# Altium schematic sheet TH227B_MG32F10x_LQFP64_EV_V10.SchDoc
size 309 x 233 mm
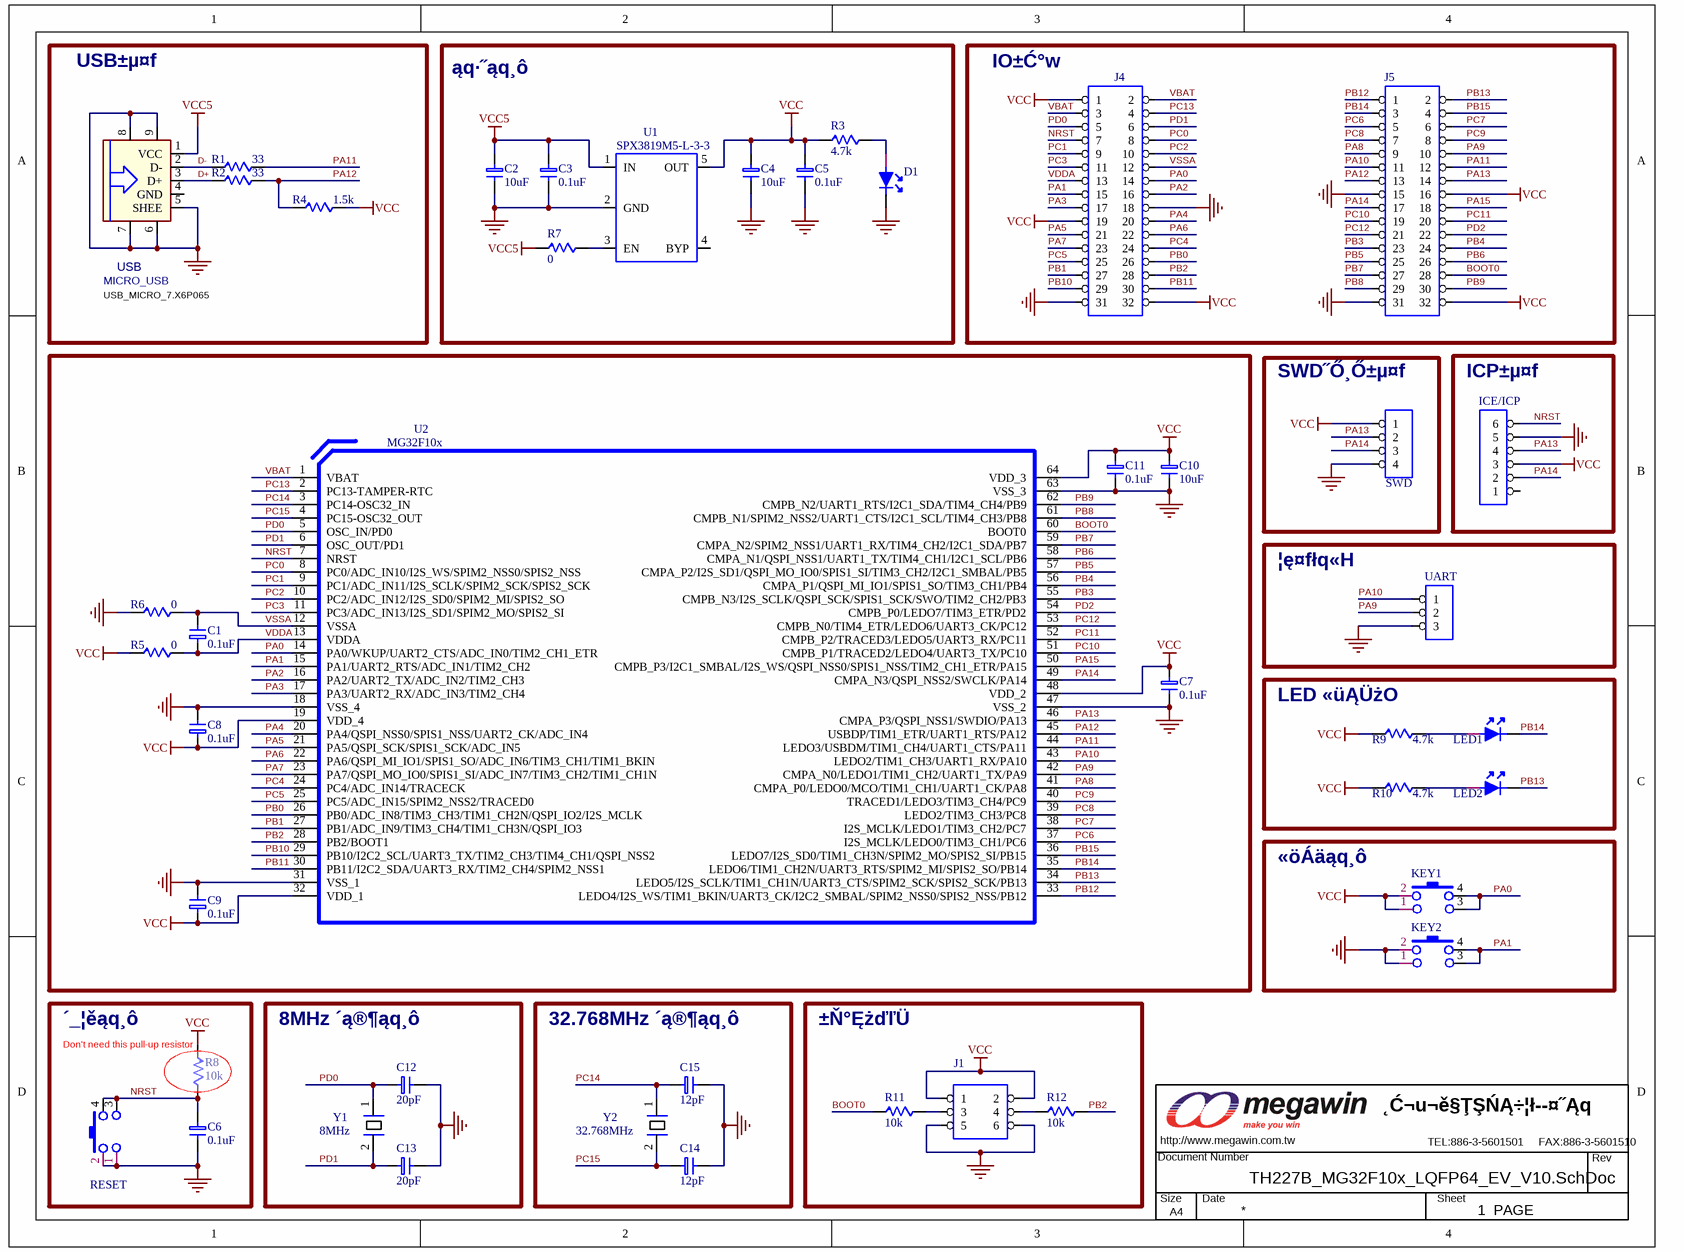
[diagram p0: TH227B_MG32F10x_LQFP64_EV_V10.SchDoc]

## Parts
C1  0.1uF  [0603_C]
C2  10uF  [0805_C]
C3  0.1uF  [0603_C]
C4  10uF  [0805_C]
C5  0.1uF  [0603_C]
C6  0.1uF  [0603_C]
C7  0.1uF  [0603_C]
C8  0.1uF  [0603_C]
C9  0.1uF  [0603_C]
C10  10uF  [0805_C]
C11  0.1uF  [0603_C]
C12  20pF  [0603_C]
C13  20pF  [0603_C]
C14  12pF  [0603_C]
C15  12pF  [0603_C]
D1  (no value)  [0805_LED_S1]
ICE/ICP  (no value)  [PS6P254F_90]
J1  CON3X2  [HDR-3X2]  (value not drawn)
J4  CON16X2  [HDR2X16_MR]  (value not drawn)
J5  CON16X2  [HDR2X16_MR]  (value not drawn)
KEY1  SW-PB4  [TSW DIP-6*6*6]  (value not drawn)
KEY2  SW-PB4  [TSW DIP-6*6*6]  (value not drawn)
LED1  (no value)  [0805_LED_S1]
LED2  (no value)  [0805_LED_S1]
MW1  MW-A4  [MEGAWIN_3.4]  (value not drawn)  (no BOM)
R1  33  [0603_R]
R2  33  [0603_R]
R3  4.7k  [0603_R]
R4  1.5k  [0603_R]
R5  0  [0603_R]
R6  0  [0603_R]
R7  0  [0603_R]
R8  10k  [0603_R]
R9  4.7k  [0603_R]
R10  4.7k  [0603_R]
R11  10k  [0603_R]
R12  10k  [0603_R]
RESET  SW-PB4  [TSW DIP-6*6*6]  (value not drawn)
SWD  CON4  [HDR-1X4]  (value not drawn)
U1  SPX3819M5-L-3-3  [SOT-23-5]
U2  MG32F10x  [LQFP64]
UART  CON3  [HDR-1X3]  (value not drawn)
USB  MICRO_USB  [USB5-micro_B-«Ř­ĘMRUSB-5B-D17xx-]
Y1  8MHz  [LC-HC-49S]
Y2  32.768MHz  [XTAL-3X8H]

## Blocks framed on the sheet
USB±µ¤f: R1 R2 R4 USB
ąq·˝ąq¸ô: C2-C5 D1 R3 R7 U1
IO±Ć°w: J4 J5
SWD˝Ő¸Ő±µ¤f: SWD
ICP±µ¤f: ICE/ICP
¦ę¤fłq«H: UART
LED «üĄÜżO: LED1 LED2 R9 R10
«öÁäąq¸ô: KEY1 KEY2
´_¦ěąq¸ô: C6 R8 RESET
8MHz ´ą®¶ąq¸ô: C12 C13 Y1
32.768MHz ´ą®¶ąq¸ô: C14 C15 Y2
±Ň°ĘżďľÜ: J1 R11 R12

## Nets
GND_POWER: C2.2 C3.2 C4.2 C5.2 C6.2 C7.2 C8.2 C9.2 C10.2 C11.2 C12.2 C13.2 C14.2 C15.2 D1.2 ICE/ICP.5 J1.5 J1.6 J4.18 J4.31 J5.15 J5.31 KEY2.1 KEY2.2 R6.1 RESET.1 RESET.2 SWD.4 U1.2(GND) U2.18(VSS_4) U2.31(VSS_1) U2.47(VSS_2) U2.63(VSS_3) UART.3 USB.5(SHEE) USB.6 USB.7 USB.8 USB.9
VCC: C4.1 C5.1 C7.1 C8.1 C9.1 C10.1 C11.1 ICE/ICP.3 J1.1 J1.2 J4.1 J4.19 J4.32 J5.16 J5.32 KEY1.1 KEY1.2 R3.1 R4.2 R5.1 R8.1 R9.1 R10.1 SWD.1 U1.5(OUT) U2.19(VDD_4) U2.32(VDD_1) U2.48(VDD_2) U2.64(VDD_3)
VCC5: C2.1 C3.1 R7.1 U1.1(IN) USB.1(VCC)
BOOT0: J5.28 R11.1 U2.60(BOOT0)
D+: R2.1 USB.3(D+)
D-: R1.1 USB.2(D-)
NRST: C6.1 ICE/ICP.6 J4.7 R8.2 RESET.3 RESET.4 U2.7(NRST)
PA0: J4.14 KEY1.3 KEY1.4 U2.14(PA0/WKUP/UART2_CTS/ADC_IN0/TIM2_CH1_ETR)
PA1: J4.15 KEY2.3 KEY2.4 U2.15(PA1/UART2_RTS/ADC_IN1/TIM2_CH2)
PA2: J4.16 U2.16(PA2/UART2_TX/ADC_IN2/TIM2_CH3)
PA3: J4.17 U2.17(PA3/UART2_RX/ADC_IN3/TIM2_CH4)
PA4: J4.20 U2.20(PA4/QSPI_NSS0/SPIS1_NSS/UART2_CK/ADC_IN4)
PA5: J4.21 U2.21(PA5/QSPI_SCK/SPIS1_SCK/ADC_IN5)
PA6: J4.22 U2.22(PA6/QSPI_MI_IO1/SPIS1_SO/ADC_IN6/TIM3_CH1/TIM1_BKIN)
PA7: J4.23 U2.23(PA7/QSPI_MO_IO0/SPIS1_SI/ADC_IN7/TIM3_CH2/TIM1_CH1N)
PA8: J5.9 U2.41(CMPA_P0/LEDO0/MCO/TIM1_CH1/UART1_CK/PA8)
PA9: J5.10 U2.42(CMPA_N0/LEDO1/TIM1_CH2/UART1_TX/PA9) UART.2
PA10: J5.11 U2.43(LEDO2/TIM1_CH3/UART1_RX/PA10) UART.1
PA11: J5.12 R1.2 U2.44(LEDO3/USBDM/TIM1_CH4/UART1_CTS/PA11)
PA12: J5.13 R2.2 R4.1 U2.45(USBDP/TIM1_ETR/UART1_RTS/PA12)
PA13: ICE/ICP.4 J5.14 SWD.2 U2.46(CMPA_P3/QSPI_NSS1/SWDIO/PA13)
PA14: ICE/ICP.2 J5.17 SWD.3 U2.49(CMPA_N3/QSPI_NSS2/SWCLK/PA14)
PA15: J5.18 U2.50(CMPB_P3/I2C1_SMBAL/I2S_WS/QSPI_NSS0/SPIS1_NSS/TIM2_CH1_ETR/PA15)
PB0: J4.26 U2.26(PB0/ADC_IN8/TIM3_CH3/TIM1_CH2N/QSPI_IO2/I2S_MCLK)
PB1: J4.27 U2.27(PB1/ADC_IN9/TIM3_CH4/TIM1_CH3N/QSPI_IO3)
PB2: J4.28 R12.2 U2.28(PB2/BOOT1)
PB3: J5.23 U2.55(CMPB_N3/I2S_SCLK/QSPI_SCK/SPIS1_SCK/SWO/TIM2_CH2/PB3)
PB4: J5.24 U2.56(CMPA_P1/QSPI_MI_IO1/SPIS1_SO/TIM3_CH1/PB4)
PB5: J5.25 U2.57(CMPA_P2/I2S_SD1/QSPI_MO_IO0/SPIS1_SI/TIM3_CH2/I2C1_SMBAL/PB5)
PB6: J5.26 U2.58(CMPA_N1/QSPI_NSS1/UART1_TX/TIM4_CH1/I2C1_SCL/PB6)
PB7: J5.27 U2.59(CMPA_N2/SPIM2_NSS1/UART1_RX/TIM4_CH2/I2C1_SDA/PB7)
PB8: J5.29 U2.61(CMPB_N1/SPIM2_NSS2/UART1_CTS/I2C1_SCL/TIM4_CH3/PB8)
PB9: J5.30 U2.62(CMPB_N2/UART1_RTS/I2C1_SDA/TIM4_CH4/PB9)
PB10: J4.29 U2.29(PB10/I2C2_SCL/UART3_TX/TIM2_CH3/TIM4_CH1/QSPI_NSS2)
PB11: J4.30 U2.30(PB11/I2C2_SDA/UART3_RX/TIM2_CH4/SPIM2_NSS1)
PB12: J5.1 U2.33(LEDO4/I2S_WS/TIM1_BKIN/UART3_CK/I2C2_SMBAL/SPIM2_NSS0/SPIS2_NSS/PB12)
PB13: J5.2 LED2.2 U2.34(LEDO5/I2S_SCLK/TIM1_CH1N/UART3_CTS/SPIM2_SCK/SPIS2_SCK/PB13)
PB14: J5.3 LED1.2 U2.35(LEDO6/TIM1_CH2N/UART3_RTS/SPIM2_MI/SPIS2_SO/PB14)
PB15: J5.4 U2.36(LEDO7/I2S_SD0/TIM1_CH3N/SPIM2_MO/SPIS2_SI/PB15)
PC0: J4.8 U2.8(PC0/ADC_IN10/I2S_WS/SPIM2_NSS0/SPIS2_NSS)
PC1: J4.9 U2.9(PC1/ADC_IN11/I2S_SCLK/SPIM2_SCK/SPIS2_SCK)
PC2: J4.10 U2.10(PC2/ADC_IN12/I2S_SD0/SPIM2_MI/SPIS2_SO)
PC3: J4.11 U2.11(PC3/ADC_IN13/I2S_SD1/SPIM2_MO/SPIS2_SI)
PC4: J4.24 U2.24(PC4/ADC_IN14/TRACECK)
PC5: J4.25 U2.25(PC5/ADC_IN15/SPIM2_NSS2/TRACED0)
PC6: J5.5 U2.37(I2S_MCLK/LEDO0/TIM3_CH1/PC6)
PC7: J5.6 U2.38(I2S_MCLK/LEDO1/TIM3_CH2/PC7)
PC8: J5.7 U2.39(LEDO2/TIM3_CH3/PC8)
PC9: J5.8 U2.40(TRACED1/LEDO3/TIM3_CH4/PC9)
PC10: J5.19 U2.51(CMPB_P1/TRACED2/LEDO4/UART3_TX/PC10)
PC11: J5.20 U2.52(CMPB_P2/TRACED3/LEDO5/UART3_RX/PC11)
PC12: J5.21 U2.53(CMPB_N0/TIM4_ETR/LEDO6/UART3_CK/PC12)
PC13: J4.4 U2.2(PC13-TAMPER-RTC)
PC14: C15.1 U2.3(PC14-OSC32_IN) Y2.1
PC15: C14.1 U2.4(PC15-OSC32_OUT) Y2.2
PD0: C12.1 J4.5 U2.5(OSC_IN/PD0) Y1.1
PD1: C13.1 J4.6 U2.6(OSC_OUT/PD1) Y1.2
PD2: J5.22 U2.54(CMPB_P0/LEDO7/TIM3_ETR/PD2)
VBAT: J4.2 J4.3 U2.1(VBAT)
VDDA: C1.1 J4.13 R5.2 U2.13(VDDA)
VSSA: C1.2 J4.12 R6.2 U2.12(VSSA)
NetD1_1: D1.1 R3.2
NetJ1_3: J1.3 R11.2
NetJ1_4: J1.4 R12.1
NetLED1_1: LED1.1 R9.2
NetLED2_1: LED2.1 R10.2
NetR7_2: R7.2 U1.3(EN)

Not connected (* = marked no-connect by the designer): ICE/ICP 1; U1 4(BYP); USB 4(GND)

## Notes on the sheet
- USB_MICRO_7.X6P065
- (near R8) Don't need this pull-up resistor

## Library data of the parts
C1-C15 = CAP: Capacitor
D1 LED1 LED2 = LED_SC
ICE/ICP = CON6: Connector
MW1 = MW_A4
R1-R12 = RES1
SWD = CON4: Connector
U1 = IC5_SPX3819M5-L-3-3
U2 = IC64_MG32F10x
UART = CON3: Connector
USB = USB_Micro
Y1 Y2 = XTAL: Crystal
